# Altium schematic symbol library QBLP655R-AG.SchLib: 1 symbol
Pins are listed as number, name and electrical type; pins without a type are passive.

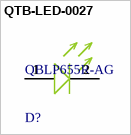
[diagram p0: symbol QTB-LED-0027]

## QTB-LED-0027
designator D?, comment QBLP655R-AG
LED YELLOW/GREEN CLEAR 1205 SMD, REVERSE MOUNT; Manufacturer: QT Brightek (QTB); Lens Size: 1.2mm; Luminous Intensity: 25mcd; Test Current: 20mA; Lens Color: Colorless; Lens Style: Square with Flat Top; Forward Voltage: 2.0V; Wavelength - Dominant: 570nm; Viewing Angle: 140º
footprint QBLP655R-AG
pins: 1 ANODE (+), 2 CATHODE (-)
